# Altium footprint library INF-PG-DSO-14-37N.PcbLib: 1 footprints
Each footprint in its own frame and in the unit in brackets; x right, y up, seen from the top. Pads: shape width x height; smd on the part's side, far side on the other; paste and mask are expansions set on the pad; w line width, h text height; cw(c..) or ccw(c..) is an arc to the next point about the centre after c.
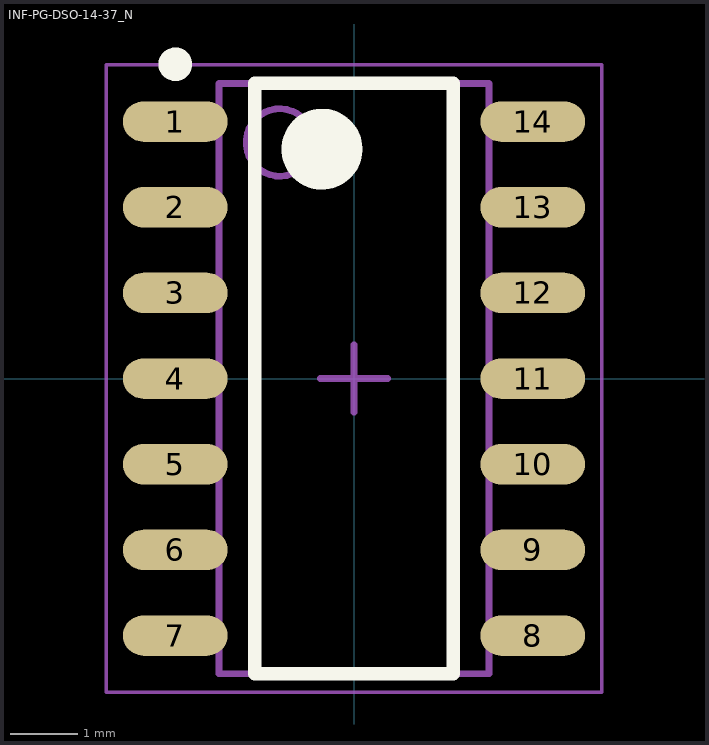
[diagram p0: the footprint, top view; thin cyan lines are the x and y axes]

## INF-PG-DSO-14-37_N [mm] "SOP, 14-Leads, Body 8.65x3.9mm, Pitch 1.27mm, IPC Medium Density"
height 1.75
pads (14):
  oval 1.55x0.6 smd: 1(-2.65,3.81) 2(-2.65,2.54) 3(-2.65,1.27) 4(-2.65,0) 5(-2.65,-1.27) 6(-2.65,-2.54) 7(-2.65,-3.81) 8(2.65,-3.81) 9(2.65,-2.54) 10(2.65,-1.27) 11(2.65,0) 12(2.65,1.27) 13(2.65,2.54) 14(2.65,3.81)
Top Overlay:
  circle w0.6: c-0.475,3.4 r0.3
  circle w0.25: c-2.65,4.66 r0.125
  lines w0.2: -1.475,-4.375 1.475,-4.375 1.475,4.375 -1.475,4.375 -1.475,-4.375
Mechanical 13:
  circle w0.1: c-1.1,3.5 r0.5
  lines w0.1: -2,-4.375 2,-4.375 2,4.375 -2,4.375 -2,-4.375
Mechanical 15:
  lines w0.05: -3.675,-4.65 3.675,-4.65 3.675,4.65 -3.675,4.65 -3.675,-4.65
  lines w0.1: -0.5,0 0.5,0 ; 0,-0.5 0,0.5
3D body: height 1.75, standoff 0.11, extent -2,-4.375 2,4.375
